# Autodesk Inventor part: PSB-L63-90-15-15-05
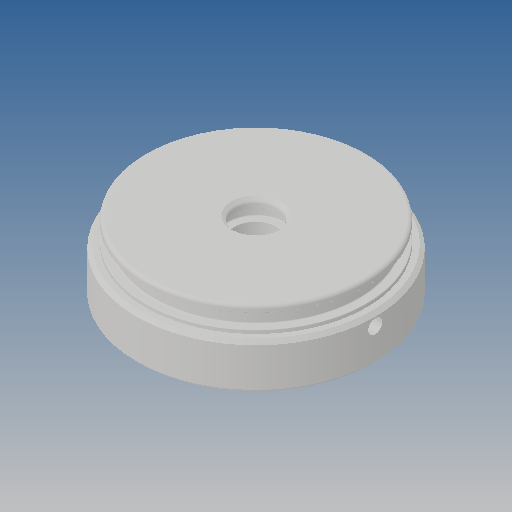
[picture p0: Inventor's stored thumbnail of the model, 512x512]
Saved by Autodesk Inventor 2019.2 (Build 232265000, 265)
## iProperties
Created: 2013-04
Part Number: PSB-L63-90-15-15-05
Material: Ogólny
Document SubType Name: Modeling
Designer: CADENGINEERING4
Density: 1 g/cm^3
Appearance: Domyślna
Author: CADENGINEERING4
Revision Number: ÈÎºÎ
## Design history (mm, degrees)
feature "ÇÐ³ý-À­Éì5"
node "Bryła1"
